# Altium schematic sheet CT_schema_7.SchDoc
size 277 x 170 mm
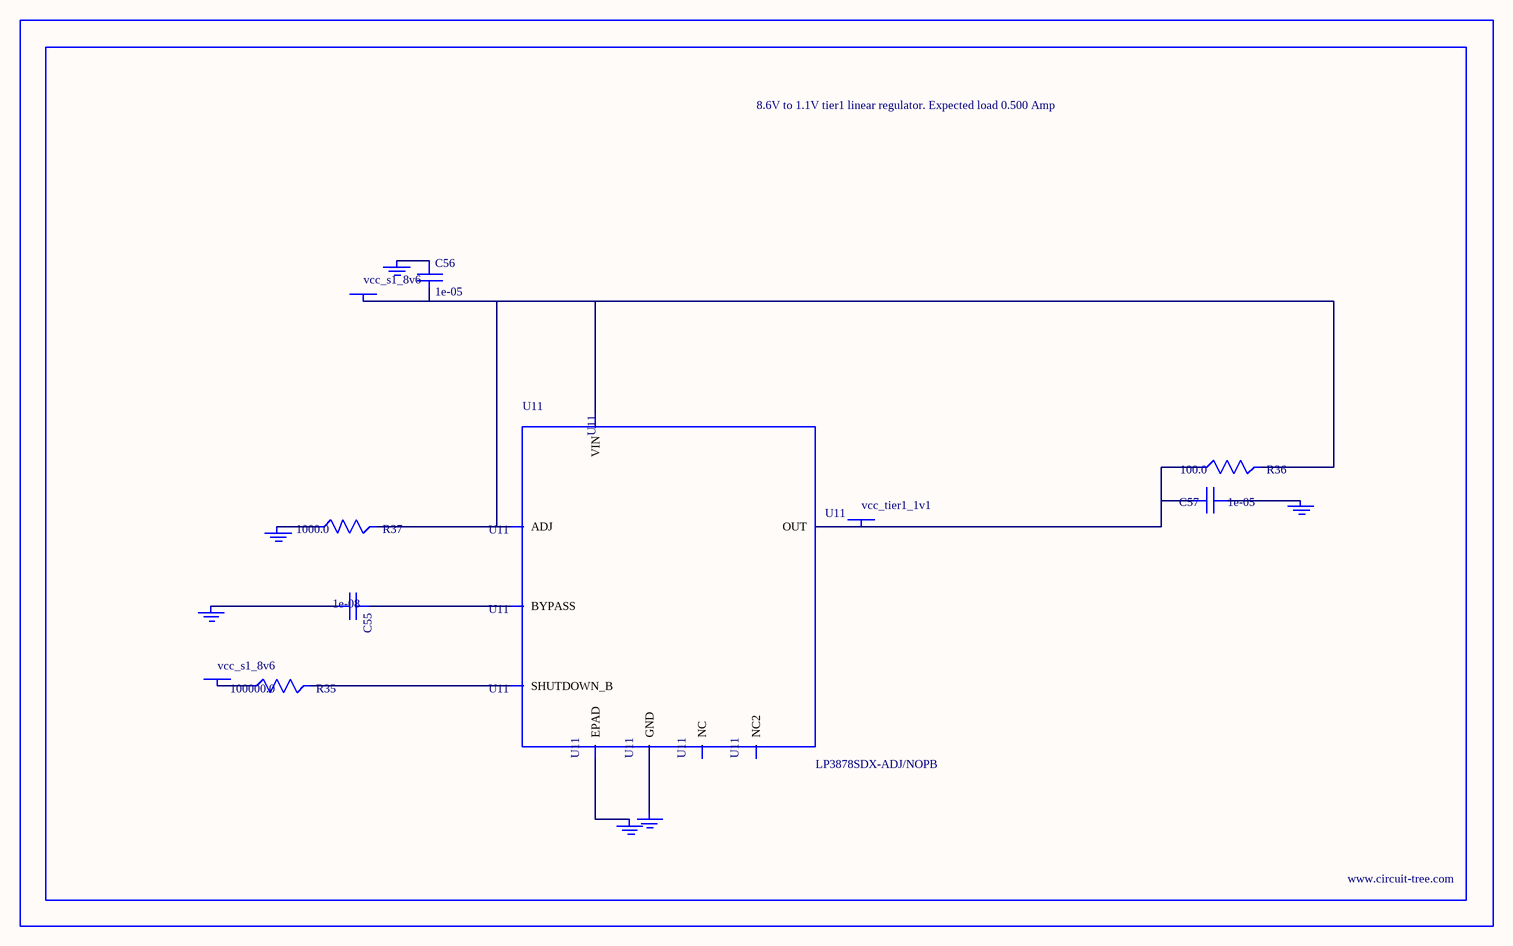
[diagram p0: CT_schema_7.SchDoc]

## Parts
BORDER6  (no value)
C55  1e-08  [C0402]
C56  1e-05  [C1206]
C57  1e-05  [C0805]
GND_INSTANCE_6_0  (no value)
GND_INSTANCE_6_1  (no value)
GND_INSTANCE_6_2  (no value)
GND_INSTANCE_6_3  (no value)
GND_INSTANCE_6_4  (no value)
GND_INSTANCE_6_5  (no value)
POWER_INSTANCE_6_0  vcc_s1_8v6
POWER_INSTANCE_6_1  vcc_s1_8v6
POWER_INSTANCE_6_2  vcc_tier1_1v1
R35  100000.0  [R0603]
R36  100.0  [R0603]
R37  1000.0  [R0603]
U11  LP3878SDX-ADJ/NOPB  [WSON-8]

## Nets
NetC55_1: C55.1 U11.1(BYPASS)
NetC55_2: C55.2 GND_INSTANCE_6_0.0(GND)
NetC56_1: C56.1 GND_INSTANCE_6_1.0(GND)
NetC56_2: C56.2 POWER_INSTANCE_6_0.0(PWR) R36.2 R37.2 U11.4(VIN) U11.6(ADJ)
NetC57_1: C57.1 GND_INSTANCE_6_2.0(GND)
NetC57_2: C57.2 POWER_INSTANCE_6_2.0(PWR) R36.1 U11.5(OUT)
NetGND_INSTANCE_6_3_0: GND_INSTANCE_6_3.0(GND) R37.1
NetGND_INSTANCE_6_4_0: GND_INSTANCE_6_4.0(GND) U11.PAD(EPAD)
NetGND_INSTANCE_6_5_0: GND_INSTANCE_6_5.0(GND) U11.3(GND)
NetPOWER_INSTANCE_6_1_0: POWER_INSTANCE_6_1.0(PWR) R35.1
NetR35_2: R35.2 U11.8(SHUTDOWN_B)

Not connected (* = marked no-connect by the designer): U11 2(NC) 7(NC2)

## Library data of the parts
BORDER6 = BORDER_PAGE6
C55 = C0402C103K3RAC
C56 = C1206C106K3RACTU
C57 = GRM219R60J106ME19D
GND_INSTANCE_6_0-GND_INSTANCE_6_5 = GND
POWER_INSTANCE_6_0-POWER_INSTANCE_6_2 = PWR
R35 = RC0603JR-07100KL
R36 = RC0603JR-07100RL
R37 = RC0603JR-071KL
